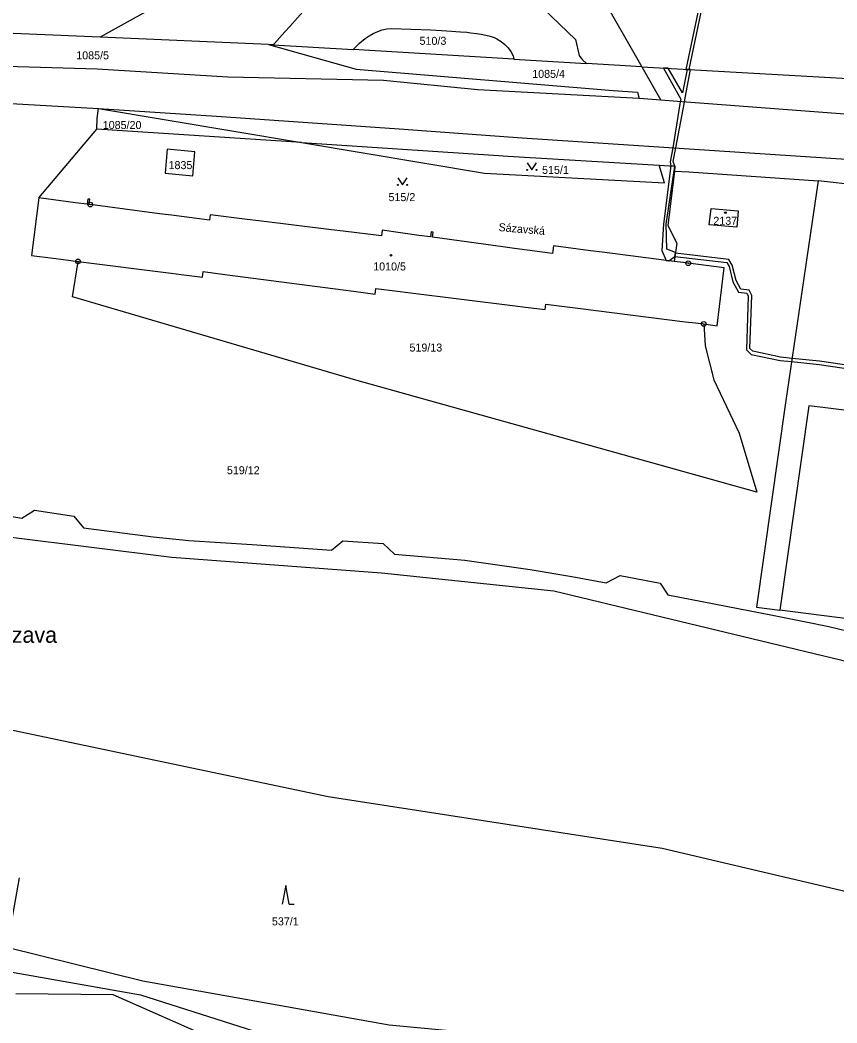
# Model space of a CAD drawing. Extents: x -680203 to -673936, y -1102717 to -1093650.
# Drawn here: x -679355.9 to -679182.5, y -1098763.5 to -1098550.5 of the extents above; entities that cross this region are included whole.
import ezdxf

# ---------------------------------------------------------------- set-up
doc = ezdxf.new("R2010")
doc.units = 0
for name, color, linetype in [('SOxx02xx_Koleje_param další_Popis10', 7, 'Continuous'), ('SOxx02xx_Staničení_Popis10', 7, 'Continuous'), ('SOxxxxxx_Koleje_hlavní_body_Popis10', 7, 'Continuous'), ('SOxxxxxx_Koleje_LN_parametry_Popis10', 7, 'Continuous'), ('SOxxxxxx_Koleje_param další_Popis10', 7, 'Continuous'), ('SOxxxxxx_Osa_bod_P', 7, 'Continuous'), ('x_prac', 7, 'Continuous')]:
    doc.layers.add(name, color=color, linetype=linetype)

msp = doc.modelspace()

# ---------------------------------------------------------------- linework, layer by layer
at = {"layer": 'SOxx02xx_Koleje_param další_Popis10'}
for centre, radius in [((-679340.98, -1098589.71), 0.5), ((-679340.98, -1098589.71), 0.0303), ((-679343.58, -1098601.77), 0.5), ((-679343.58, -1098601.77), 0.0303), ((-679214.03, -1098602.16), 0.5), ((-679214.03, -1098602.16), 0.0303), ((-679210.72, -1098615.07), 0.5), ((-679210.72, -1098615.07), 0.0303)]:
    msp.add_circle(centre, radius, dxfattribs=at)
at = {"layer": 'SOxxxxxx_Koleje_hlavní_body_Popis10'}
for p, q in [((-679299.47, -1098734.31), (-679300.22, -1098738.31)), ((-679298.72, -1098738.31), (-679299.47, -1098734.31)), ((-679298.72, -1098738.31), (-679297.72, -1098738.31))]:
    msp.add_line(p, q, dxfattribs=at)
for points in [[(-679248.25, -1098580.84), (-679247.25, -1098582.34), (-679246.25, -1098580.84)], [(-679275.67, -1098584.03), (-679274.67, -1098585.53), (-679273.67, -1098584.03)]]:
    msp.add_lwpolyline(points, dxfattribs=at)
for centre in [(-679248.25, -1098582.34), (-679246.25, -1098582.34), (-679275.67, -1098585.53), (-679273.67, -1098585.53)]:
    msp.add_circle(centre, 0.1, dxfattribs=at)
at = {"layer": 'SOxxxxxx_Koleje_LN_parametry_Popis10'}
for points in [[(-679210.29, -1098540.74), (-679214.53, -1098560.98), (-679213.82, -1098561.02), (-679209.63, -1098540.98)], [(-679177.06, -1098624.29), (-679186.13, -1098622.97), (-679191.99, -1098622.37), (-679194.43, -1098622.13), (-679200.33, -1098620.87), (-679200.97, -1098620.27), (-679200.56, -1098609.01), (-679201.12, -1098607.87), (-679202.88, -1098607.65), (-679203.88, -1098605.84), (-679204.71, -1098602.6), (-679205.4, -1098601.38), (-679216.75, -1098600.01), (-679216.84, -1098600.71), (-679205.84, -1098602.04), (-679205.36, -1098602.86), (-679204.54, -1098606.09), (-679203.33, -1098608.3), (-679201.58, -1098608.52), (-679201.27, -1098609.16), (-679201.68, -1098620.56), (-679200.67, -1098621.52), (-679194.54, -1098622.82), (-679192.1, -1098623.06), (-679186.22, -1098623.67), (-679177.13, -1098624.99)]]:
    msp.add_lwpolyline(points, dxfattribs=at)
for points in [[(-679219.31, -1098560.7), (-679215.62, -1098567.33), (-679215.71, -1098567.86), (-679217.33, -1098577.62), (-679217.83, -1098580.6), (-679217.7, -1098581.47), (-679216.86, -1098581.52), (-679217.21, -1098580.54), (-679216.66, -1098577.66), (-679214.82, -1098567.93), (-679214.65, -1098567.02), (-679213.52, -1098561.03), (-679214.26, -1098560.99), (-679215.23, -1098565.97), (-679218.31, -1098560.76)], [(-679218.71, -1098593.87), (-679216.86, -1098581.52), (-679217.7, -1098581.47), (-679219.31, -1098593.83), (-679219.63, -1098599.47), (-679218.72, -1098601.57), (-679218.14, -1098601.64), (-679216.84, -1098600.71), (-679216.74, -1098599.88), (-679218.6, -1098599.16)]]:
    msp.add_lwpolyline(points, close=True, dxfattribs=at)
at = {"layer": 'SOxxxxxx_Koleje_param další_Popis10'}
for centre in [(-679206.12, -1098591.42), (-679277.15, -1098600.48)]:
    msp.add_circle(centre, 0.175, dxfattribs=at)
at = {"layer": 'x_prac'}
for p, q in [((-679249.02, -1098516.43), (-679223.89, -1098560.44)), ((-679338.89, -1098554.17), (-679374.27, -1098552.65)), ((-679303.14, -1098555.72), (-679338.89, -1098554.17)), ((-679302.12, -1098555.78), (-679303.14, -1098555.72)), ((-679302.12, -1098555.78), (-679285.13, -1098556.79)), ((-679251.07, -1098558.82), (-679285.13, -1098556.79)), ((-679251.07, -1098558.82), (-679235.65, -1098559.74)), ((-679223.89, -1098560.44), (-679235.65, -1098559.74)), ((-679223.89, -1098560.44), (-679219.83, -1098567.51)), ((-679219.83, -1098567.51), (-679224.46, -1098567.17)), ((-679339.23, -1098569.31), (-679296.12, -1098576.52)), ((-679351.92, -1098588.27), (-679339.57, -1098573.66)), ((-679296.12, -1098576.52), (-679339.57, -1098573.66)), ((-679296.12, -1098576.52), (-679254.32, -1098579.28)), ((-679254.32, -1098579.28), (-679252.3, -1098579.39)), ((-679252.3, -1098579.39), (-679220.2, -1098581.32)), ((-679220.2, -1098581.32), (-679216.86, -1098581.52)), ((-679216.86, -1098581.52), (-679216.92, -1098582.58)), ((-679176.28, -1098585.84), (-679186.41, -1098584.64))]:
    msp.add_line(p, q, dxfattribs=at)
for points in [[(-679249.02, -1098516.43), (-679323.48, -1098545.53), (-679338.89, -1098554.17)], [(-679302.12, -1098555.78), (-679301.88, -1098555.51), (-679299.66, -1098553.02), (-679298.63, -1098551.88), (-679293.76, -1098546.38)], [(-679246.55, -1098546.42), (-679237.94, -1098554.65), (-679237.18, -1098558.04), (-679236.85, -1098558.55), (-679236.51, -1098558.95), (-679235.65, -1098559.74)], [(-679285.13, -1098556.79), (-679283.83, -1098555.41), (-679283.41, -1098555.06), (-679282.63, -1098554.44), (-679281.79, -1098553.89), (-679280.9, -1098553.39), (-679279.94, -1098552.94), (-679279, -1098552.62), (-679278.04, -1098552.39), (-679277.04, -1098552.28), (-679268.68, -1098552.62), (-679265.26, -1098552.82), (-679262.35, -1098552.98), (-679261.01, -1098553.1), (-679260.21, -1098553.19), (-679258.99, -1098553.34), (-679258.01, -1098553.5), (-679257.03, -1098553.71), (-679256.07, -1098553.96), (-679255.26, -1098554.23), (-679254.66, -1098554.49), (-679253.73, -1098555.05), (-679252.98, -1098555.68), (-679252.27, -1098556.42), (-679251.66, -1098557.22), (-679251.23, -1098558.11), (-679251.07, -1098558.82)], [(-679224.46, -1098567.17), (-679258.68, -1098565.34), (-679278.74, -1098563.33), (-679311.75, -1098562.64), (-679339.5, -1098560.92), (-679368.52, -1098560.1), (-679477.74, -1098558.09), (-679478.16, -1098555.47)], [(-679303.14, -1098555.72), (-679284.51, -1098560.97), (-679229.99, -1098565.44), (-679224.82, -1098565.82), (-679224.46, -1098567.17)], [(-678903.28, -1098557.95), (-678928.91, -1098564.28), (-678943.76, -1098567.85), (-678966.88, -1098572.76), (-678971.6, -1098573.69), (-678982.27, -1098575.37), (-678989.19, -1098576.65), (-679006.16, -1098578.84), (-679015.52, -1098579.01), (-679023.33, -1098579.28), (-679037.21, -1098579.21), (-679042.25, -1098579.5), (-679050.47, -1098579.2), (-679077.53, -1098577.77), (-679090.67, -1098576.96), (-679104.61, -1098575.94), (-679131.51, -1098574.1), (-679132.75, -1098574.02), (-679142.38, -1098573.41), (-679180.81, -1098570.47), (-679213.51, -1098568.04), (-679217.22, -1098567.74), (-679219.83, -1098567.51)], [(-679223.89, -1098560.44), (-679180.06, -1098562.95), (-679177.32, -1098564.87), (-679138.93, -1098568.96), (-679134.88, -1098566.97), (-679130.85, -1098567.19), (-679085.75, -1098570.24), (-679082.28, -1098570.5), (-679032.12, -1098573.17), (-679028.63, -1098573.39), (-679027.48, -1098573)], [(-679396.42, -1098566.65), (-679382.65, -1098566.82), (-679339.23, -1098569.31)], [(-679339.57, -1098573.66), (-679339.49, -1098571.37), (-679339.23, -1098569.31)], [(-679339.23, -1098569.31), (-679314.15, -1098570.93), (-679275.4, -1098573.63), (-679249.26, -1098575.51), (-679144.01, -1098582.45), (-679082.62, -1098586.45), (-679071.23, -1098587.19)], [(-679296.12, -1098576.52), (-679257.3, -1098583.02), (-679219.06, -1098585.1), (-679220.2, -1098581.32)], [(-679318.76, -1098578.48), (-679324.67, -1098577.96), (-679325.11, -1098583.04), (-679319.21, -1098583.57), (-679318.76, -1098578.48)], [(-679216.92, -1098582.58), (-679218.34, -1098594.18), (-679216.48, -1098597.89), (-679216.98, -1098601.79)], [(-679216.92, -1098582.58), (-679213.93, -1098582.73), (-679186.41, -1098584.64)], [(-679186.41, -1098584.64), (-679188.77, -1098600.53), (-679193.39, -1098631.82), (-679199.54, -1098675.2), (-679194.58, -1098675.84)], [(-679351.92, -1098588.27), (-679353.45, -1098600.52), (-679348.85, -1098601.1), (-679346.65, -1098601.38), (-679343.58, -1098601.77)], [(-679216.98, -1098601.79), (-679232.33, -1098599.82), (-679234.81, -1098599.5), (-679242.64, -1098598.5), (-679242.84, -1098600.1), (-679250.9, -1098599), (-679253.42, -1098598.66), (-679268.35, -1098596.63), (-679268.2, -1098595.54), (-679268.6, -1098595.49), (-679268.75, -1098596.57), (-679271.22, -1098596.24), (-679279.03, -1098595.17), (-679279.17, -1098596.35), (-679287.27, -1098595.35), (-679289.8, -1098595.04), (-679305.2, -1098593.14), (-679307.69, -1098592.84), (-679315.54, -1098591.87), (-679315.69, -1098593.04), (-679323.76, -1098591.98), (-679326.28, -1098591.64), (-679340.98, -1098589.71), (-679341.23, -1098589.68), (-679341.09, -1098588.59), (-679341.48, -1098588.54), (-679341.62, -1098589.63), (-679344.1, -1098589.3), (-679351.92, -1098588.27)], [(-679203.73, -1098594.51), (-679209.56, -1098593.98), (-679209.18, -1098590.52), (-679203.42, -1098591.05), (-679203.73, -1098594.51)], [(-679210.72, -1098615.07), (-679210.46, -1098619.69), (-679208.58, -1098626.95), (-679203.19, -1098638.28), (-679199.49, -1098650.76), (-679284.62, -1098627.01), (-679344.76, -1098609.31), (-679343.58, -1098601.77)], [(-679343.58, -1098601.77), (-679323.83, -1098604.28), (-679321.7, -1098604.55), (-679317.13, -1098605.13)], [(-679210.72, -1098615.07), (-679207.92, -1098615.43), (-679206.38, -1098603.15), (-679214.03, -1098602.16), (-679214.45, -1098602.11), (-679216.98, -1098601.79)], [(-679317.13, -1098605.13), (-679316.98, -1098603.95), (-679312.39, -1098604.55)], [(-679312.39, -1098604.55), (-679310.2, -1098604.83), (-679287.26, -1098607.82), (-679285.07, -1098608.11), (-679280.48, -1098608.7), (-679280.34, -1098607.53), (-679275.77, -1098608.1), (-679273.59, -1098608.37), (-679250.76, -1098611.22), (-679248.58, -1098611.49), (-679244.41, -1098612.01), (-679244.27, -1098610.84), (-679239.7, -1098611.42), (-679237.46, -1098611.7), (-679214.67, -1098614.58), (-679212.49, -1098614.85), (-679210.72, -1098615.07)], [(-679125.78, -1098640.22), (-679185.45, -1098632.8), (-679188.43, -1098632.43), (-679194.58, -1098675.84)], [(-679111.46, -1098705.74), (-679132.56, -1098698.29), (-679200.49, -1098681.93), (-679242.57, -1098671.79), (-679279.14, -1098668.03), (-679323.68, -1098664.68), (-679357.75, -1098660.39), (-679374.2, -1098655.82), (-679412.72, -1098645.66)], [(-679362.35, -1098655.17), (-679355.52, -1098656.3), (-679352.84, -1098654.59), (-679344.46, -1098655.89), (-679342.39, -1098658.34), (-679327.6, -1098660.27), (-679320.05, -1098661.07), (-679306.63, -1098661.93), (-679289.77, -1098663.08), (-679287.36, -1098661.13), (-679278.78, -1098661.69), (-679276.37, -1098663.97), (-679261.48, -1098665.25), (-679248.61, -1098667.06), (-679247.62, -1098667.2), (-679238.74, -1098668.7), (-679231.43, -1098670.05), (-679228.46, -1098668.52), (-679219.99, -1098670.15), (-679218.37, -1098672.63), (-679196.16, -1098676.94), (-679189.07, -1098678.31), (-679184.17, -1098679.33), (-679178.31, -1098680.75)], [(-678902.07, -1098794.22), (-678994.34, -1098793.28), (-679089.82, -1098757.03), (-679219.58, -1098726.45), (-679290.48, -1098715.53), (-679368.28, -1098699.15), (-679441.53, -1098681.76), (-679497.79, -1098663.1)], [(-679158.45, -1098687.03), (-679161.59, -1098686.63), (-679160.84, -1098680.19), (-679194.58, -1098675.84)], [(-679356.08, -1098732.7), (-679358.69, -1098747.46), (-679329.82, -1098754.62), (-679277.52, -1098763.92), (-679215.95, -1098769.72)], [(-679359.57, -1098752.39), (-679330.34, -1098757.57), (-679280.56, -1098773.45), (-679238.96, -1098777.52)], [(-679317.4, -1098765.82), (-679336.1, -1098757.53), (-679356.78, -1098757.36)]]:
    msp.add_lwpolyline(points, dxfattribs=at)

# ---------------------------------------------------------------- texts
at = {"layer": 'SOxx02xx_Staničení_Popis10'}
msp.add_text('Sázavská', height=1.7, rotation=355, dxfattribs=at).set_placement((-679254.35, -1098595.31))
msp.add_text('Sázava', height=3.4, dxfattribs=at).set_placement((-679363.2, -1098682.79))
at = {"layer": 'SOxxxxxx_Osa_bod_P'}
for s, p in [('510/3', (-679271.07, -1098555.77)), ('1085/5', (-679343.96, -1098558.85)), ('1085/4', (-679247.15, -1098562.79)), ('1085/20', (-679338.33, -1098573.65)), ('1835', (-679324.36, -1098582.17)), ('515/1', (-679245.06, -1098583.19)), ('515/2', (-679277.67, -1098588.97)), ('2137', (-679208.7, -1098594)), ('1010/5', (-679280.91, -1098603.7)), ('519/13', (-679273.21, -1098620.92)), ('519/12', (-679311.97, -1098646.98)), ('537/1', (-679302.41, -1098742.81))]:
    msp.add_text(s, height=1.7, dxfattribs=at).set_placement(p)

doc.saveas('drawing.dxf')
